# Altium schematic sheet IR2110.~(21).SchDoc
size A4
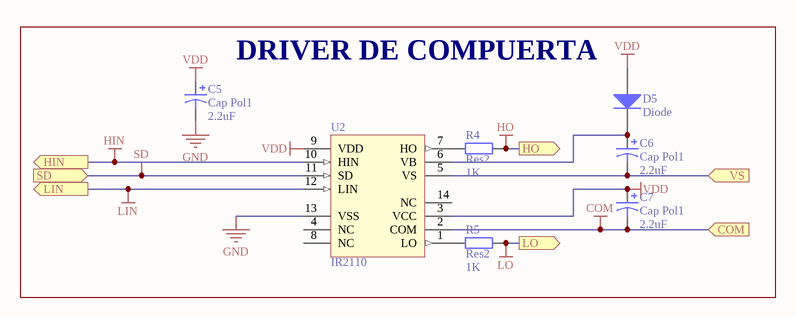
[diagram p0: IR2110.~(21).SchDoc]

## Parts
C5  Cap Pol1  value 2.2uF  [CAPPR2.5-6.3X5]
C6  Cap Pol1  value 2.2uF  [CAPPR2.5-6.3X5]
C7  Cap Pol1  value 2.2uF  [CAPPR2.5-6.3X5]
D5  Diode  [DO-204AL]
R4  Res2  value 1K  [AXIAL-0.3]
R5  Res2  value 1K  [AXIAL-0.3]
U2  IR2110  [PDIP14]

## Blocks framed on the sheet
DRIVER DE COMPUERTA: C5-C7 D5 R4 R5 U2

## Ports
COM (in), HIN (out), HO (out), LIN (out), LO (out), SD (in), VS (in)

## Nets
COM: C7.2 U2.2(COM) ; port COM
GND: C5.2 U2.13(VSS)
HIN: U2.10(HIN) ; port HIN
HO: R4.2 ; port HO
LIN: U2.12(LIN) ; port LIN
LO: R5.2 ; port LO
SD: U2.11(SD) ; port SD
VDD: C5.1 C7.1 D5.1(A) U2.3(VCC) U2.9(VDD)
VS: C6.2 U2.5(VS) ; port VS
NetC6_1: C6.1 D5.2(K) U2.6(VB)
NetR4_1: R4.1 U2.7(HO)
NetR5_1: R5.1 U2.1(LO)

Not connected (* = marked no-connect by the designer): U2 4(NC) 8(NC) 14(NC)

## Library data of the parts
C5-C7 = Cap Pol1: Polarized Capacitor (Radial)
D5 = Diode: Default Diode
R4 R5 = Res2: Resistor
U2 = IR2110: High and Low Side Driver; Note: Pins 4, 8 and 14 are not connected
